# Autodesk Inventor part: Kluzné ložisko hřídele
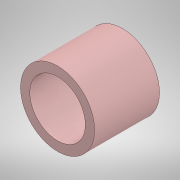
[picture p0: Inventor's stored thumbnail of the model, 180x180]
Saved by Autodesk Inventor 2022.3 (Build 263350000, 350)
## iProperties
Created: 2025-11
Part Number: Kluzné ložisko hřídele
Material: Všeobecné
Document SubType Name: Modeling
Designer: Hra42
Density: 1 g/cm^3
Appearance: Výchozí
Author: Hra42
Sending System: SolidWorks 2012
Last Author: Hra42
Last Saved: 2025-11-14
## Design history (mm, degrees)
feature "T_X2_011B_X0_leso1"
node "Těleso1"
